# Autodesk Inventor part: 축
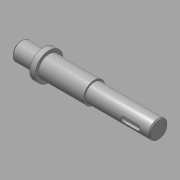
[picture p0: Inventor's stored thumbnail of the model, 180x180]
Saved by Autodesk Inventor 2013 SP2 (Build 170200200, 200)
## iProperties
Created: 2015-09
Part Number: 축
Material: 강철, 연강
Document SubType Name: Modeling
Designer: mduedu
Density: 7.86 g/cm^3
Mass: 263.424 g
Surface Area: 86.4309 cm^2
Volume: 33.5145 cm^3
Author: mduedu
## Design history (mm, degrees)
sketch "스케치1"
  geometry: L1 (-64, 0)-(64, 0); L2 (-64, 0)-(-64, 8.5); L3 (-64, 8.5)-(-43, 8.5); L4 (-43, 8.5)-(-43, 13); L5 (-43, 13)-(-38, 13); L6 (-38, 13)-(-38, 10); L7 (-38, 10)-(4, 10); L8 (4, 10)-(4, 8.5); L9 (4, 8.5)-(64, 8.5); L10 (64, 8.5)-(64, 0); 2 further points
  constraints: 20 end point, 5 parallel, 2 horizontal, 2 perpendicular, 1 coincident, 1 midpoint, 1 vertical
  dimensions: "d0" = 128 distance of L1.start L1.end; "d2" = 5 distance of L4.end L5.end; "d3" = 42 distance of L6.end L7.end; "d4" = 60 distance of L8.end L9.end; "d5" = 17 diameter of L3 L1; "d6" = 17 diameter of L9 L1; "d7" = 20 diameter of L7 L1; "d8" = 26 diameter of L5 L1
revolve "회전1" sketch "스케치1" stored, may be unused: angle "d9" = 90 deg
node "작업 평면1"
sketch "스케치2"
  geometry: L1 (5.5, 2.5)-(18.5, 2.5); L2 (18.5, -2.5)-(5.5, -2.5); L3 (5.5, 2.5)-(18.5, -2.5); L4 (18.5, 2.5)-(5.5, -2.5); L5 (30, -8.5)-(30, 8.5) reference; A1 r 2.5 centre (5.5, 0) between (5.5, 2.5) and (5.5, -2.5); A2 r 2.5 centre (18.5, 0) between (18.5, -2.5) and (18.5, 2.5); 2 further points
  constraints: 8 end point, 4 point on circle, 4 tangent, 2 centre point, 2 midpoint, 1 horizontal, 1 horizontal alignment, 1 parallel
  dimensions: "d10" = 18 dimension on A2 A1; "d12" = 9 distance edge to line of A2 L5; "d13" = 5 distance between parallel lines of L2 L1
extrude "돌출1" cut sketch "스케치2" distance "d14" = 3; taper "d15" = 0 deg
node "작업 평면2"
sketch "스케치4"
  geometry: L1 (7, -3)-(-9, -3); L2 (-9, 3)-(7, 3); L3 (-21, 10)-(-21, -10) reference; A1 r 3 centre (-9, 0) between (-9, 3) and (-9, -3); A2 r 3 centre (7, 0) between (7, -3) and (7, 3); 1 further point
  constraints: 4 end point, 4 point on circle, 4 tangent, 2 centre point, 1 horizontal, 1 horizontal alignment, 1 parallel
  dimensions: "d16" = 22 dimension on A1 A2; "d18" = 6 distance between parallel lines of L2 L1; "d19" = 9 distance edge to line of A1 L3
extrude "돌출2" cut sketch "스케치4" distance "d20" = 3.5; taper "d21" = 0 deg
sketch "스케치5"
  geometry: L1 (4, 8.5)-(64, 8.5) reference; L2 (4, -8.5)-(64, -8.5) reference; L3 (37, 8.5)-(37, -8.5); L4 (37, -6.5)-(35, -8.5); L5 (37, -8.5)-(35, -8.5); L6 (37, -8.5)-(37, -6.5); L7 (4, -10)-(4, 10) reference; 1 further point
  constraints: 8 end point, 4 point on line, 1 collinear, 1 perpendicular
  dimensions: "d22" = 4 diameter of L4.end L3; "d24" = 45 deg angle of L3 L4; "d26" = 33 distance between parallel lines of L3 L7
revolve "회전2" sketch "스케치5" stored, may be unused: angle "d27" = 90 deg
chamfer "모따기1" distance "d28" = 1; stored, may be unused: second distance "d29" = 2, angle "d30" = 45 deg
sketch "스케치6"
  geometry: L1 (37, -6.5)-(35, -8.5) reference; L2 (37, -6.5)-(39, -8.5) reference; 2 further points
  constraints: 1 coincident
node "솔리드1"
